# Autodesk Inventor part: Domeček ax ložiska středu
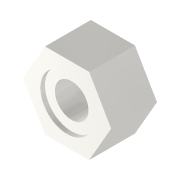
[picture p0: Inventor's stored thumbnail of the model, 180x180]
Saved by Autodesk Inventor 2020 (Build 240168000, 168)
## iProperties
Created: 2025-03
Part Number: Domeček ax ložiska středu
Material: Ocel
Document SubType Name: Modeling
Designer: doma
Density: 7.85 g/cm^3
Appearance: Ocel
Author: doma
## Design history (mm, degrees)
sketch "Náčrt1"
  geometry: L1 (14.434, 25)-(28.868, 0); L2 (28.868, 0)-(14.434, -25); L3 (14.434, -25)-(-14.434, -25); L4 (-14.434, -25)-(-28.868, 0); L5 (-28.868, 0)-(-14.434, 25); L6 (-14.434, 25)-(14.434, 25); 2 further points
  constraints: 12 end point, 1 coincident, 13 other
  dimensions: "d0" = 50 distance between parallel lines of L3 L6
extrude "Vysunutí1" new body sketch "Náčrt1" distance "d1" = 30; taper "d2" = 0 deg
sketch "Náčrt2"
  geometry: C1 r 17.5 at (0, 0); 1 further point
  constraints: 1 centre point, 1 coincident
  dimensions: "d3" = 35 diameter of C1
extrude "Vysunutí2" cut sketch "Náčrt2" distance "d4" = 3; taper "d5" = 0 deg
sketch "Náčrt3"
  geometry: C1 r 11 at (0, 0); 1 further point
  constraints: 1 centre point, 1 coincident
  dimensions: "d6" = 22 diameter of C1
extrude "Vysunutí3" cut sketch "Náčrt3" extent not by distance; stored distance "d7" = 0; taper "d8" = 0 deg
sketch "Náčrt4"
  geometry: C1 r 17 at (0, 0); 1 further point
  constraints: 1 centre point, 1 coincident
  dimensions: "d9" = 34 diameter of C1
extrude "Vysunutí4" cut sketch "Náčrt4" distance "d10" = 15; taper "d11" = 0 deg
node "Těleso1"
